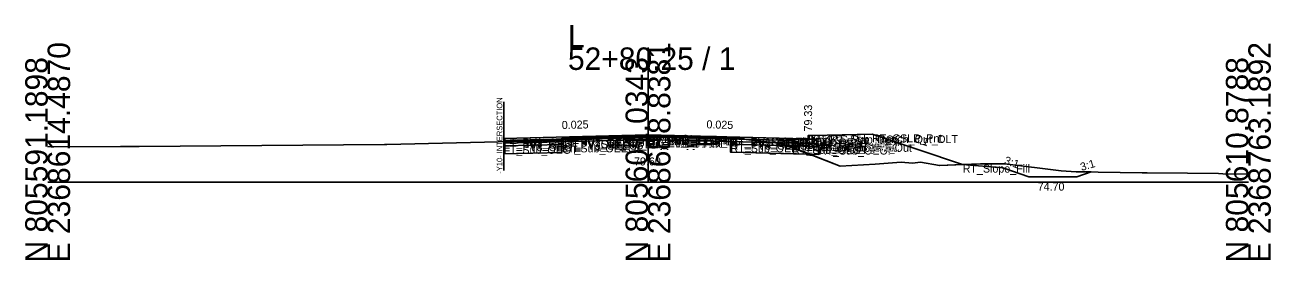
# Model space of a CAD drawing. Extents: x -26 to 8153, y -10 to 9520.
# Drawn here: x 4997.2 to 5152.8, y 490.3 to 519.6 of the extents above; entities that cross this region are included whole.
import ezdxf

# ---------------------------------------------------------------- set-up
doc = ezdxf.new("R2010")
doc.units = 0
for name, color, linetype in [('Exist CMT Pavement', 7, 'Continuous'), ('Exist Cross Section Cell', 7, 'Continuous'), ('Exist XS Center Line Elevation Label', 7, 'Continuous'), ('Exist XS Ground Line', 7, 'Continuous'), ('Prop CMT Conc Surface', 7, 'Continuous'), ('Prop CMT Concrete Structures', 7, 'Continuous'), ('Prop CMT Ditch DDE', 7, 'Continuous'), ('Prop CMT Pvmt Course 1', 7, 'Continuous'), ('Prop CMT Pvmt Course 1 CG', 7, 'Continuous'), ('Prop CMT Pvmt Course 1 Wedge', 7, 'Continuous'), ('Prop CMT Pvmt Course 2', 7, 'Continuous'), ('Prop CMT Pvmt Course 2 Wedge', 7, 'Continuous'), ('Prop CMT Pvmt Course 3', 7, 'Continuous'), ('Prop CMT Pvmt Course 3 Wedge', 7, 'Continuous'), ('Prop CMT Pvmt Surface', 7, 'Continuous'), ('Prop CMT Pvmt Wedge Surface 1', 7, 'Continuous'), ('Prop CMT Pvmt Wedge Surface 2', 7, 'Continuous'), ('Prop CMT Pvmt Wedge Surface 3', 7, 'Continuous'), ('Prop CMT Shallow Undercut', 7, 'Continuous'), ('Prop CMT Shallow Undercut Boundary', 7, 'Continuous'), ('Prop CMT Shear Line', 7, 'Continuous'), ('Prop CMT Slope Grass', 7, 'Continuous'), ('Prop CMT Subgrade Earthwork', 7, 'Continuous'), ('Prop XS Earthwork Shape', 7, 'Continuous'), ('Prop XS Hydro Elevations', 7, 'Continuous'), ('Prop XS SE Text', 7, 'Continuous'), ('Prop XS Side Slope Text', 7, 'Continuous'), ('Prop XS Subgrade Earthwork', 7, 'Continuous'), ('Scratch_Level_2', 7, 'Continuous'), ('Scratch_Level_6', 7, 'Continuous')]:
    doc.layers.add(name, color=color, linetype=linetype)

msp = doc.modelspace()

# ---------------------------------------------------------------- linework, layer by layer
at = {"layer": 'Exist CMT Pavement'}
for p, q in [((5060.58, 505.12), (5073.03, 505.55)), ((5073.03, 505.55), (5073.83, 505.58)), ((5073.83, 505.58), (5074.53, 505.6)), ((5074.53, 505.6), (5075, 505.6)), ((5075, 505.6), (5084.89, 505.55)), ((5084.89, 505.55), (5085.31, 505.55))]:
    msp.add_line(p, q, dxfattribs=at)
at = {"layer": 'Exist Cross Section Cell'}
for p, q in [((5075, 500), (5075, 516.81)), ((5000, 500), (5075, 500)), ((5075, 500), (5150, 500))]:
    msp.add_line(p, q, dxfattribs=at)
at = {"layer": 'Exist XS Ground Line'}
for p, q in [((5000, 504.41), (5009.1, 504.46)), ((5009.1, 504.46), (5011.45, 504.47)), ((5011.45, 504.47), (5042.06, 504.72)), ((5042.06, 504.72), (5042.37, 504.72)), ((5042.37, 504.72), (5059.79, 505.11)), ((5059.79, 505.11), (5060.58, 505.12)), ((5060.58, 505.12), (5073.03, 505.55)), ((5073.03, 505.55), (5073.83, 505.58)), ((5073.83, 505.58), (5074.53, 505.6)), ((5074.53, 505.6), (5075, 505.6)), ((5075, 505.6), (5084.89, 505.55)), ((5084.89, 505.55), (5085.31, 505.55)), ((5085.31, 505.55), (5086.12, 505.46)), ((5086.12, 505.46), (5091.66, 504.82)), ((5091.66, 504.82), (5093.14, 504.29)), ((5093.14, 504.29), (5099, 502.03)), ((5099, 502.03), (5103.37, 502.27)), ((5103.37, 502.27), (5106.62, 502.5)), ((5106.62, 502.5), (5108.06, 502.37)), ((5108.06, 502.37), (5109.03, 502.51)), ((5109.03, 502.51), (5111.4, 502.09)), ((5111.4, 502.09), (5116.54, 502.32)), ((5116.54, 502.32), (5119.56, 502.32)), ((5119.56, 502.32), (5126.63, 501.44)), ((5126.63, 501.44), (5128.47, 501.32)), ((5128.47, 501.32), (5136.72, 501.19)), ((5136.72, 501.19), (5137.38, 501.18)), ((5137.38, 501.18), (5142.38, 501.12)), ((5142.38, 501.12), (5146.29, 501.08)), ((5146.29, 501.08), (5146.8, 501.06)), ((5146.8, 501.06), (5150, 501))]:
    msp.add_line(p, q, dxfattribs=at)
at = {"layer": 'Prop CMT Conc Surface'}
for points in [[(5093, 505.46), (5095, 505.33)], [(5095, 505.33), (5095, 505.83), (5095.5, 505.83)]]:
    msp.add_lwpolyline(points, dxfattribs=at)
at = {"layer": 'Prop CMT Concrete Structures'}
for points in [[(5093, 505.46), (5095, 505.33), (5095, 505.83), (5095.5, 505.83)], [(5095.5, 505.83), (5095.5, 504.81), (5093, 504.88)], [(5093, 504.88), (5093, 505.46)]]:
    msp.add_lwpolyline(points, dxfattribs=at)
at = {"layer": 'Prop CMT Ditch DDE'}
for p, q in [((5114.29, 502.22), (5114.31, 502.21)), ((5119.31, 501.79), (5114.31, 502.21)), ((5122.58, 500.7), (5119.31, 501.79)), ((5122.58, 500.7), (5128.58, 500.7)), ((5130.35, 501.29), (5128.58, 500.7))]:
    msp.add_line(p, q, dxfattribs=at)
at = {"layer": 'Prop CMT Pvmt Course 1'}
for points in [[(5075, 505.91), (5057, 505.46)], [(5057, 505.46), (5057, 505.21)], [(5057, 505.21), (5064.25, 505.39)], [(5064.25, 505.52), (5075, 505.79)], [(5064.25, 505.39), (5064.25, 505.52)], [(5075, 505.66), (5075, 505.91)], [(5075, 505.91), (5093, 505.46)], [(5075, 505.66), (5075, 505.91)], [(5075, 505.79), (5075, 505.66), (5075, 505.66)], [(5085.31, 505.53), (5075, 505.79)], [(5075, 505.79), (5075, 505.66), (5075, 505.66)], [(5085.31, 505.4), (5085.31, 505.53)], [(5093, 505.21), (5085.31, 505.4)], [(5093, 505.46), (5093, 505.21)]]:
    msp.add_lwpolyline(points, dxfattribs=at)
at = {"layer": 'Prop CMT Pvmt Course 1 CG'}
for points in [[(5093, 504.88), (5096, 504.8), (5096.34, 504.46)], [(5093, 504.55), (5093, 504.88)], [(5096.34, 504.46), (5093, 504.55)]]:
    msp.add_lwpolyline(points, dxfattribs=at)
at = {"layer": 'Prop CMT Pvmt Course 1 Wedge'}
for points in [[(5075, 505.79), (5064.25, 505.52)], [(5075, 505.79), (5085.31, 505.53)]]:
    msp.add_lwpolyline(points, dxfattribs=at)
at = {"layer": 'Prop CMT Pvmt Course 2'}
for points in [[(5064.25, 505.39), (5057, 505.21)], [(5057, 505.21), (5057, 504.88)], [(5057, 504.88), (5064.25, 505.06)], [(5064.25, 505.06), (5064.25, 505.39)], [(5085.31, 505.07), (5085.31, 505.4)], [(5085.31, 505.4), (5093, 505.21)], [(5093, 504.88), (5085.31, 505.07)], [(5093, 505.21), (5093, 504.88)]]:
    msp.add_lwpolyline(points, dxfattribs=at)
at = {"layer": 'Prop CMT Pvmt Course 2 Wedge'}
for points in [[(5075, 505.66), (5064.25, 505.39)], [(5075, 505.66), (5085.31, 505.4)]]:
    msp.add_lwpolyline(points, dxfattribs=at)
at = {"layer": 'Prop CMT Pvmt Course 3'}
for points in [[(5064.25, 505.06), (5057, 504.88)], [(5057, 504.88), (5057, 504.55)], [(5057, 504.55), (5064.25, 504.73)], [(5064.25, 504.73), (5064.25, 505.06)], [(5085.31, 505.07), (5093, 504.88)], [(5085.31, 504.74), (5085.31, 505.07)], [(5093, 504.55), (5085.31, 504.74)], [(5093, 504.88), (5093, 504.55)]]:
    msp.add_lwpolyline(points, dxfattribs=at)
at = {"layer": 'Prop CMT Pvmt Course 3 Wedge'}
for points in [[(5075, 505.33), (5064.25, 505.06)], [(5075, 505.33), (5085.31, 505.07)]]:
    msp.add_lwpolyline(points, dxfattribs=at)
at = {"layer": 'Prop CMT Pvmt Surface'}
for points in [[(5075, 505.91), (5057, 505.46), (5057, 505.04)], [(5075, 505.91), (5093, 505.46)]]:
    msp.add_lwpolyline(points, dxfattribs=at)
at = {"layer": 'Prop CMT Pvmt Wedge Surface 1'}
for points in [[(5057, 505.21), (5057, 505.46)], [(5064.25, 505.39), (5057, 505.21)], [(5075, 505.79), (5064.25, 505.52)], [(5064.25, 505.52), (5064.25, 505.39)], [(5075, 505.79), (5085.31, 505.53)], [(5085.31, 505.53), (5085.31, 505.4)], [(5085.31, 505.4), (5093, 505.21)], [(5093, 505.21), (5093, 505.46)]]:
    msp.add_lwpolyline(points, dxfattribs=at)
at = {"layer": 'Prop CMT Pvmt Wedge Surface 2'}
for points in [[(5075, 505.66), (5057, 505.21)], [(5057, 505.21), (5057, 505.46)], [(5075, 505.66), (5093, 505.21)], [(5093, 505.21), (5093, 505.46)]]:
    msp.add_lwpolyline(points, dxfattribs=at)
at = {"layer": 'Prop CMT Pvmt Wedge Surface 3'}
for points in [[(5057, 504.88), (5057, 505.46)], [(5075, 505.33), (5057, 504.88)], [(5075, 505.33), (5093, 504.88)], [(5093, 504.88), (5093, 505.46)]]:
    msp.add_lwpolyline(points, dxfattribs=at)
at = {"layer": 'Prop CMT Shallow Undercut'}
for p, q in [((5064.25, 504.73), (5057, 504.55)), ((5057, 504.55), (5057, 503.55)), ((5064.25, 503.73), (5064.25, 504.73)), ((5057, 503.55), (5064.25, 503.73))]:
    msp.add_line(p, q, dxfattribs=at)
msp.add_lwpolyline([(5085.31, 503.74), (5095.21, 503.49), (5093.14, 504.29), (5092.38, 504.56), (5085.31, 504.74)], close=True, dxfattribs=at)
at = {"layer": 'Prop CMT Shallow Undercut Boundary'}
for p, q in [((5057, 504.55), (5057, 503.55)), ((5064.25, 504.73), (5064.25, 503.73)), ((5085.31, 504.74), (5085.31, 503.74)), ((5096.34, 504.46), (5096.34, 503.46)), ((5057, 503.55), (5064.25, 503.73)), ((5085.31, 503.74), (5096.34, 503.46))]:
    msp.add_line(p, q, dxfattribs=at)
at = {"layer": 'Prop CMT Shear Line'}
msp.add_line((5057, 501.47), (5057, 510.04), dxfattribs=at)
at = {"layer": 'Prop CMT Slope Grass'}
msp.add_lwpolyline([(5095.5, 505.83), (5103, 505.98), (5114.29, 502.22)], dxfattribs=at)
at = {"layer": 'Prop CMT Subgrade Earthwork'}
for points in [[(5064.25, 504.73), (5057, 504.55)], [(5064.25, 504.73), (5064.25, 505.25)], [(5085.31, 504.74), (5085.29, 505.55)], [(5085.31, 504.74), (5093, 504.55)], [(5093, 504.55), (5096.34, 504.46), (5097.75, 505.88)]]:
    msp.add_lwpolyline(points, dxfattribs=at)
at = {"layer": 'Prop XS Earthwork Shape'}
for p, q in [((5116.54, 502.32), (5114.29, 502.22)), ((5114.29, 502.22), (5114.31, 502.21)), ((5114.31, 502.21), (5119.31, 501.79)), ((5119.56, 502.32), (5116.54, 502.32)), ((5119.31, 501.79), (5122.58, 500.7)), ((5126.63, 501.44), (5119.56, 502.32)), ((5128.47, 501.32), (5126.63, 501.44)), ((5130.35, 501.29), (5128.47, 501.32)), ((5122.58, 500.7), (5128.58, 500.7)), ((5128.58, 500.7), (5130.35, 501.29))]:
    msp.add_line(p, q, dxfattribs=at)
for points in [[(5097.75, 505.88), (5103, 505.98), (5114.29, 502.22), (5111.4, 502.09), (5109.03, 502.51), (5108.06, 502.37), (5106.62, 502.5), (5103.37, 502.27), (5099, 502.03), (5095.21, 503.49), (5096.34, 503.46), (5096.34, 504.46)], [(5064.25, 504.73), (5064.25, 503.73), (5057, 503.55), (5057, 504.55)], [(5064.25, 504.73), (5064.25, 503.73), (5057, 503.55), (5057, 504.55)], [(5085.31, 505.55), (5086.12, 505.46), (5091.66, 504.82), (5092.38, 504.56), (5085.31, 504.74), (5085.29, 505.55)], [(5093.14, 504.29), (5095.21, 503.49), (5085.31, 503.74), (5085.31, 504.74), (5092.38, 504.56)], [(5093.14, 504.29), (5095.21, 503.49), (5096.34, 503.46), (5096.34, 504.46), (5093, 504.55), (5092.38, 504.56)]]:
    msp.add_lwpolyline(points, close=True, dxfattribs=at)
at = {"layer": 'Prop XS Subgrade Earthwork'}
for p, q in [((5057, 504.55), (5064.25, 504.73)), ((5096.34, 504.46), (5085.31, 504.74))]:
    msp.add_line(p, q, dxfattribs=at)
at = {"layer": 'Scratch_Level_6'}
for p, q in [((5064.25, 504.73), (5057, 504.55)), ((5057, 504.55), (5057, 503.55)), ((5064.25, 503.73), (5064.25, 504.73)), ((5057, 503.55), (5064.25, 503.73))]:
    msp.add_line(p, q, dxfattribs=at)
msp.add_lwpolyline([(5085.31, 503.74), (5095.21, 503.49), (5093.14, 504.29), (5092.38, 504.56), (5085.31, 504.74)], close=True, dxfattribs=at)

# ---------------------------------------------------------------- texts
at = {"layer": 'Exist Cross Section Cell'}
for s, p in [('L', (5065, 516.81)), ('52+80.25 / 1', (5065, 514.01))]:
    msp.add_text(s, height=2.8, dxfattribs=at).set_placement(p)
for s, p in [('E 2368614.4870', (5002.8, 490)), ('E 2368688.8381', (5077.8, 490)), ('E 2368763.1892', (5152.8, 490)), ('N 805591.1898', (5000, 490)), ('N 805601.0343', (5075, 490)), ('N 805610.8788', (5150, 490))]:
    msp.add_text(s, height=2.8, rotation=90, dxfattribs=at).set_placement(p)
at = {"layer": 'Exist XS Center Line Elevation Label'}
msp.add_text('79.60', height=1, dxfattribs=at).set_placement((5073.25, 502.1))
at = {"layer": 'Prop CMT Shear Line'}
msp.add_text('-Y10- INTERSECTION', height=0.7, rotation=90, dxfattribs=at).set_placement((5056.8, 501.07))
at = {"layer": 'Prop XS Hydro Elevations'}
msp.add_text('79.33', height=1, rotation=90, dxfattribs=at).set_placement((5095.5, 506.33))
at = {"layer": 'Prop XS SE Text'}
for rotation, p in [(1.4321, (5064.24, 506.64)), (358.5679, (5082.29, 506.73))]:
    msp.add_text('0.025', height=1, rotation=rotation, dxfattribs=at).set_placement(p)
at = {"layer": 'Prop XS Side Slope Text'}
for rotation, p in [(341.5651, (5108.14, 505.06)), (340.5375, (5119.41, 502.33)), (16.5748, (5129.17, 501.4))]:
    msp.add_text('3:1', height=1, rotation=rotation, dxfattribs=at).set_placement(p)
msp.add_text('74.70', height=1, dxfattribs=at).set_placement((5123.68, 498.96))
at = {"layer": 'Scratch_Level_2'}
for s, p in [('RT_CSLP_Pnt', (5103, 504.98)), ('LT_PV1_OEOT', (5057, 504.46)), ('LT_PV2_OEOT', (5057, 504.21)), ('LT_PV3_OEOT', (5057, 503.88)), ('LT_Sub_OEOT', (5057, 503.55)), ('LT_PV1_OEEOP', (5064.25, 504.52)), ('LT_PV2_OEEOP', (5064.25, 504.39)), ('LT_PV_OEEOP_EG', (5064.25, 504.25)), ('LT_PV3_OEEOP', (5064.25, 504.06)), ('LT_Sub_OEEOP', (5064.25, 503.73)), ('LT_PV_Sub_Tie_Out', (5064.27, 504.25)), ('PV1_PGL', (5075, 504.91)), ('RT_PV1_IEEOP', (5075, 504.79)), ('LT_PV1_IEEOP', (5075, 504.79)), ('RT_PV2_IEEOP', (5075, 504.66)), ('LT_PV2_IEEOP', (5075, 504.66)), ('PV2_PGL', (5075, 504.66)), ('RT_PV_IEEOP_EG', (5075, 504.6)), ('LT_PV_IEEOP_EG', (5075, 504.6)), ('RT_PV3_IEEOP', (5075, 504.33)), ('LT_PV3_IEEOP', (5075, 504.33)), ('RT_PV_Sub_Tie_Out', (5085.29, 504.55)), ('RT_PV_OEEOP_EG', (5085.31, 504.55)), ('RT_PV1_OEEOP', (5085.31, 504.53)), ('RT_PV2_OEEOP', (5085.31, 504.4)), ('RT_PV3_OEEOP', (5085.31, 504.07)), ('RT_Sub_OEEOP', (5085.31, 503.74)), ('RT_PV1_OEOT', (5093, 504.46)), ('RT_PV2_OEOT', (5093, 504.21)), ('RT_PV3_OEOT', (5093, 503.88)), ('RT_CG_Bot_IE', (5093, 503.88)), ('RT_Sub_OEOT', (5093, 503.55)), ('RT_CG_Top_Face', (5095, 504.83)), ('RT_CG_Top_Gut', (5095, 504.33)), ('RT_CG_Top_BOC', (5095.5, 504.83)), ('RT_CG_Bot_BOC', (5095.5, 503.81)), ('RT_CG1_Shelf_Out', (5096, 503.8)), ('RT_Sub_OEOP', (5096.34, 503.46)), ('RT_Sub_Trench_Out_DLT', (5097.75, 504.88)), ('RT_Slope_Fill', (5114.31, 501.21))]:
    msp.add_text(s, height=1, dxfattribs=at).set_placement(p)

doc.saveas('drawing.dxf')
